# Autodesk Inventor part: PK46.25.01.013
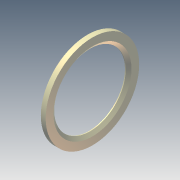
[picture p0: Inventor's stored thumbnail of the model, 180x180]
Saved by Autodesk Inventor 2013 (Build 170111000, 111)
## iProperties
Created: 2005-04
Part Number: PK46.25.01.013
Material: Nylon-6/6
Document SubType Name: Modeling
Designer: salex
Manufacturer: Standard
Standards Organization: Custom
Density: 1.13 g/cm^3
Author: salex
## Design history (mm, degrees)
sketch "Эскиз1"
  geometry: L1 (0, 0)-(22.911, 0) reference; L2 (0, 52.5)-(0, 57.5); L3 (0, 57.5)-(6, 57.5); L4 (6, 57.5)-(6, 48); L5 (6, 48)-(3, 44); L6 (3, 44)-(2, 44); L7 (2, 44)-(2, 52.5); L8 (2, 52.5)-(0, 52.5)
  constraints: 16 end point, 4 perpendicular, 2 horizontal, 2 parallel, 1 other
  dimensions: "d0" = 0 distance from line of L1.start L2; "d1" = 6 distance of L2.end L3.end; "d2" = 115 diameter of L3 L1; "d3" = 1 distance of L5.end L6.end; "d4" = 2 distance of L7.end L2.start; "d5" = 96 diameter of L4.end L1; "d6" = 105 diameter of L8 L1; "d7" = 88 diameter of L6 L1
revolve "Вращение1" sketch "Эскиз1" stored, may be unused: angle "d8" = 90 deg
body "Solid1"
